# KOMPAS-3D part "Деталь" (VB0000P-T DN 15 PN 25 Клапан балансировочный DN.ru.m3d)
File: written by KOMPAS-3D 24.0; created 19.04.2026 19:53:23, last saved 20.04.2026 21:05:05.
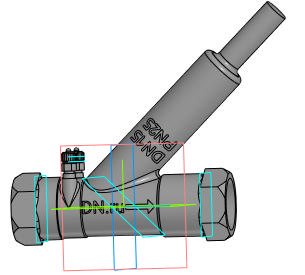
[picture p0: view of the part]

Document properties: Автор: mrdid; Полное имя файла: C:\Работа\VB0000P-T DN X PN 25 Клапан балансировочный DN.ru\DN15\исходные материалы\VB0000P-T DN 15 PN 25 Клапан балансировочный DN.ru.m3d

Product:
- Part/product: Деталь
    Масса: 0.310742

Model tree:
1. Эскиз:1
2. Элемент вращения:1
     Угол 1 = 360
3. Фаска:1  (with: Ребро.Элемент вращения:1)
     Угол = 45; Длина 1 = 3; Длина 2 = 3
4. Фаска:2  (with: Ребро.Элемент вращения:1)
     Угол = 45; Длина 1 = 2; Длина 2 = 2
5. Фаска:3  (with: Ребро.Элемент вращения:1)
     Угол = 45; Длина 1 = 1; Длина 2 = 1
6. Фаска:4  (with: Ребро.Элемент вращения:1)
     Угол = 30; Длина 1 = 3; Длина 2 = 1.73205
7. Смещенная плоскость:1  (with: Грань.Элемент вращения:1)
     Расстояние = 10
8. Эскиз:2
9. Элемент выдавливания:1  (with: Грань.Фаска:4)
     Расстояние 1 = 32.0714
10. Эскиз:3
11. Элемент выдавливания:2  (with: Грань.Фаска:4)
     Расстояние 2 = 15.6251
12. Смещенная плоскость:2  (with: Грань.Элемент вращения:1)
     Расстояние = 10
13. Эскиз:4  (with: Ребро.Фаска:4)
14. Элемент выдавливания:3  (with: Грань.Фаска:4)
     Расстояние 2 = 32.0714
15. Эскиз:5
16. Элемент выдавливания:4  (with: Грань.Фаска:4)
     Расстояние 2 = 41.0714
17. Фаска:5  (with: Ребро.Элемент выдавливания:4)
     Угол = 45; Длина 1 = 2; Длина 2 = 2
18. Плоскость под углом:1
     Угол = 45
19. Касательная плоскость:1  (with: Грань.Элемент вращения:1)
20. Эскиз:6  (with: Ребро.Фаска:3)
21. Элемент выдавливания:5  (with: Грань.Элемент вращения:1)
     Расстояние 1 = 7.02513; Расстояние 2 = 70
22. Эскиз:7  (with: Грань.Элемент вращения:1)
23. Элемент выдавливания:6  (with: Грань.Элемент вращения:1)
24. Эскиз:8  (with: Грань.Элемент выдавливания:6, Ребро.Элемент выдавливания:6)
25. Элемент выдавливания:7
     Расстояние 1 = 2
26. Эскиз:9  (with: Грань.Элемент выдавливания:7, Ребро.Элемент выдавливания:7)
27. Элемент выдавливания:8
     Расстояние 1 = 1
28. Эскиз:10  (with: Грань.Элемент выдавливания:8, Ребро.Элемент выдавливания:6)
29. Элемент выдавливания:10
     Расстояние 1 = 3
30. Эскиз:11  (with: Грань.Элемент выдавливания:10, Ребро.Элемент выдавливания:6)
31. Элемент выдавливания:11
     Расстояние 1 = 1
32. Эскиз:12  (with: Грань.Элемент выдавливания:11, Ребро.Элемент выдавливания:6)
33. Элемент выдавливания:12
     Расстояние 1 = 3
34. Эскиз:13  (with: Грань.Элемент выдавливания:12, Ребро.Элемент выдавливания:7)
35. Элемент выдавливания:13
     Расстояние 1 = 2
36. Скругление:1  (with: Ребро.Элемент выдавливания:13)
     Радиус = 1
37. Средняя плоскость:2  (with: Грань.Элемент выдавливания:12, Грань.Элемент выдавливания:10)
38. Эскиз:14  (with: Ребро.Элемент выдавливания:11)
39. Элемент выдавливания:14
     Расстояние 1 = 0.5
40. Средняя плоскость:3  (with: Грань.Элемент выдавливания:12)
41. Эскиз:15  (with: Вершина.Элемент выдавливания:14, Ребро.Элемент выдавливания:14)
42. Эскиз:16  (with: Грань.Элемент выдавливания:12, Ребро.Скругление:1)
43. Элемент выдавливания:15
     Расстояние 1 = 0.5
44. Элемент выдавливания:16  (with: Грань.Элемент выдавливания:15, Грань.Элемент выдавливания:14)
     Расстояние 1 = 1.5; Расстояние 2 = 1.75
45. Скругление:2  (with: Ребро.Элемент выдавливания:14, Ребро.Элемент выдавливания:15, Ребро.Элемент выдавливания:16)
     Радиус = 1
46. Зеркальный массив:1
47. Экземпляр ( 1 )
48. Экземпляр ( 2 )  (with: Элемент выдавливания:15, Элемент выдавливания:16, Элемент выдавливания:14, Скругление:2)
49. Скругление:3  (with: Ребро.Элемент выдавливания:5)
     Радиус = 2
50. Скругление:4  (with: Ребро.Элемент выдавливания:6)
     Радиус = 1
51. Эскиз:17  (with: Грань.Элемент выдавливания:5, Ребро.Элемент выдавливания:5)
52. Элемент выдавливания:17
     Расстояние 1 = 30
53. Скругление:5  (with: Ребро.Элемент выдавливания:17, Ребро.Элемент выдавливания:5)
     Радиус = 2
54. Скругление:6  (with: Ребро.Элемент выдавливания:4, Ребро.Элемент выдавливания:2)
     Радиус = 1
55. Эскиз:19  (with: Грань.Элемент выдавливания:5)
56. Элемент выдавливания:19  (with: Грань.Элемент выдавливания:5)
     Расстояние 1 = 9.59027; Смещение 1 = 0.2
57. Эскиз:20
58. Элемент выдавливания:20  (with: Грань.Элемент вращения:1)
     Расстояние 1 = 11.7; Смещение 1 = 0.2; Расстояние 2 = 11.7; Смещение 2 = 0.2
59. Эскиз:21
60. Элемент выдавливания:21  (with: Грань.Элемент вращения:1)
     Расстояние 1 = 11.6982; Смещение 1 = 0.2
61. Эскиз:22  (with: Ребро.Фаска:2)
62. Элемент выдавливания:22
     Расстояние 1 = 43.5; Расстояние 2 = 67.7137

Expressions: 1/2*25.4
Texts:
  Линейный размер с обрывом
  GOST 26.020 Pr3
  var3D
  Gn+T+5
  Dn+1
  Ds-1
  Ds-2
  Ds-4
